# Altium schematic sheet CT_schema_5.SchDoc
size 411 x 401 mm
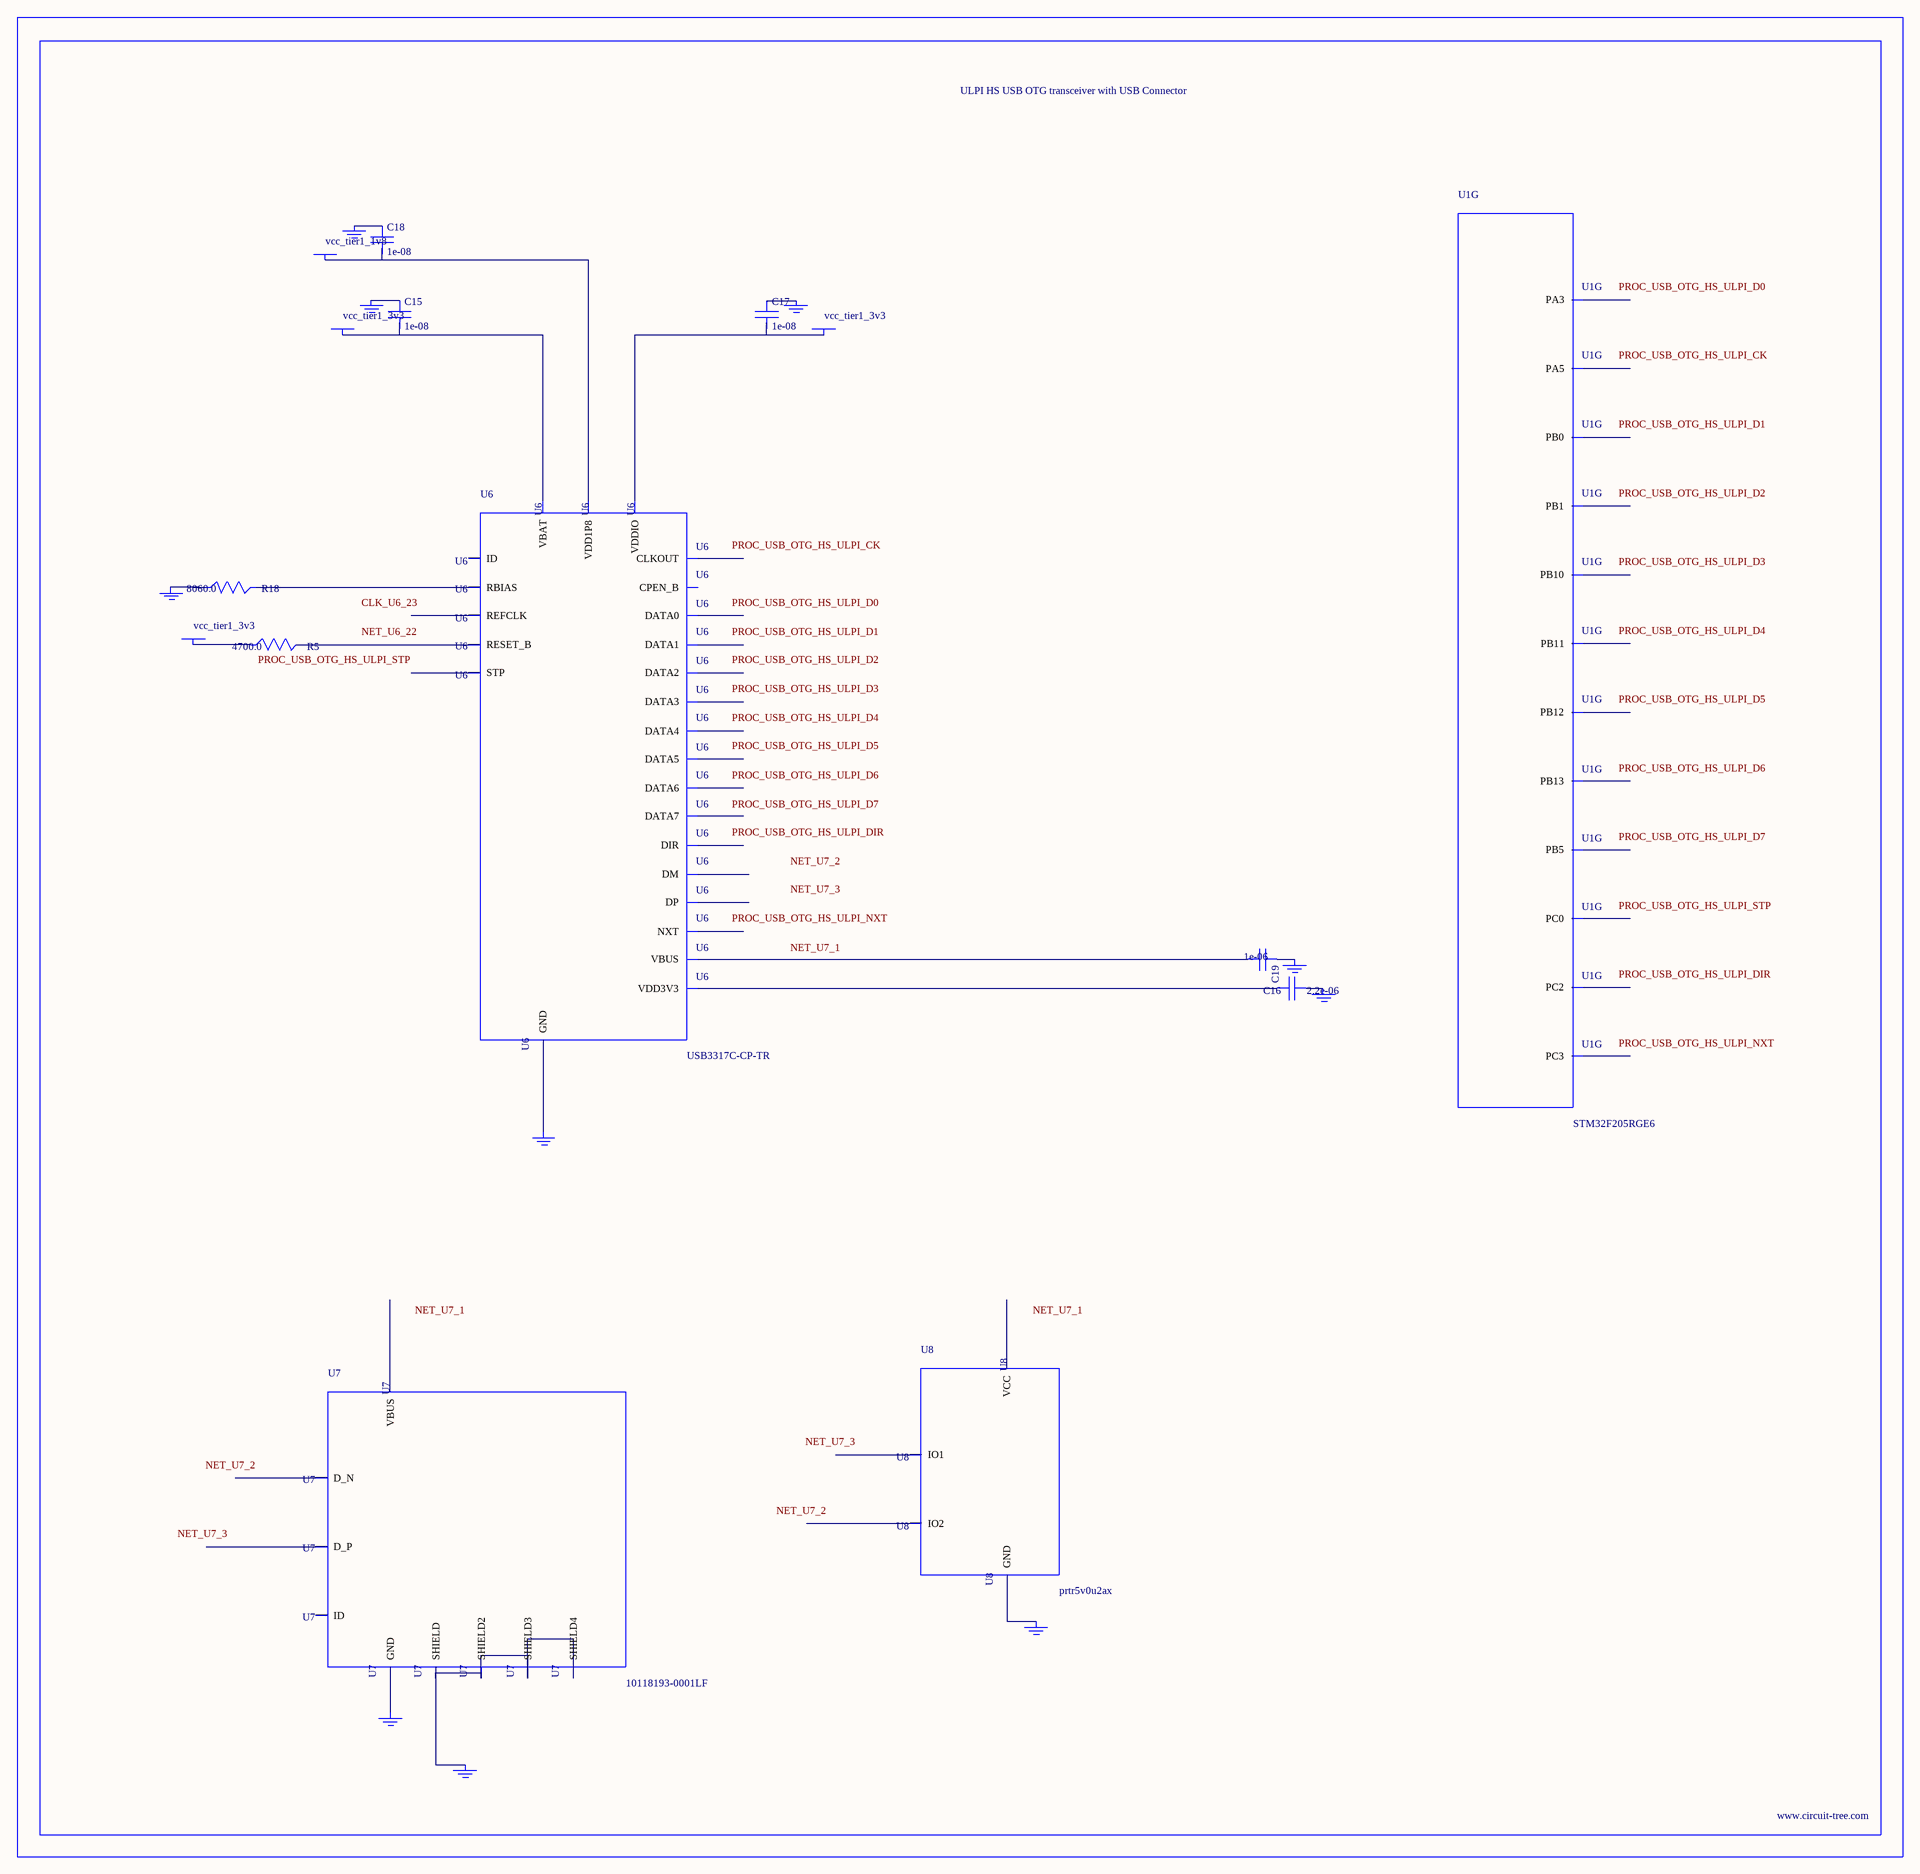
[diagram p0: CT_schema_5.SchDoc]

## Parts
BORDER4  (no value)
C15  1e-08  [C0402]
C16  2.2e-06  [C0603]
C17  1e-08  [C0402]
C18  1e-08  [C0402]
C19  1e-06  [C0603]
GND_INSTANCE_4_0  (no value)
GND_INSTANCE_4_1  (no value)
GND_INSTANCE_4_2  (no value)
GND_INSTANCE_4_3  (no value)
GND_INSTANCE_4_4  (no value)
GND_INSTANCE_4_5  (no value)
GND_INSTANCE_4_6  (no value)
GND_INSTANCE_4_7  (no value)
GND_INSTANCE_4_8  (no value)
GND_INSTANCE_4_9  (no value)
POWER_INSTANCE_4_0  vcc_tier1_3v3
POWER_INSTANCE_4_1  vcc_tier1_3v3
POWER_INSTANCE_4_2  vcc_tier1_1v8
POWER_INSTANCE_4_3  vcc_tier1_3v3
R5  4700.0  [R0603]
R18  8060.0  [R0603]
U1  STM32F205RGE6  [EWLCSP66]  (part G of 7)
U6  USB3317C-CP-TR  [QFN-24]
U7  10118193-0001LF  [FCI_10118193-0001LF]
U8  prtr5v0u2ax  [SOT143B]

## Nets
NetC15_1: C15.1 GND_INSTANCE_4_1.0(GND)
NetC15_2: C15.2 POWER_INSTANCE_4_0.0(PWR) U6.3(VBAT)
NetC16_1: C16.1 GND_INSTANCE_4_2.0(GND)
NetC16_2: C16.2 U6.4(VDD3V3)
NetC17_1: C17.1 GND_INSTANCE_4_3.0(GND)
NetC17_2: C17.2 POWER_INSTANCE_4_1.0(PWR) U6.17(VDDIO)
NetC18_1: C18.1 GND_INSTANCE_4_4.0(GND)
NetC18_2: C18.2 POWER_INSTANCE_4_2.0(PWR) U6.21(VDD1P8)
NetC19_1: C19.1 GND_INSTANCE_4_0.0(GND)
NetC19_2: C19.2 U6.2(VBUS)
NetGND_INSTANCE_4_5_0: GND_INSTANCE_4_5.0(GND) R18.1
NetGND_INSTANCE_4_6_0: GND_INSTANCE_4_6.0(GND) U6.25(GND)
NetGND_INSTANCE_4_7_0: GND_INSTANCE_4_7.0(GND) U7.6(SHIELD) U7.7(SHIELD2) U7.8(SHIELD3) U7.9(SHIELD4)
NetGND_INSTANCE_4_8_0: GND_INSTANCE_4_8.0(GND) U7.5(GND)
NetGND_INSTANCE_4_9_0: GND_INSTANCE_4_9.0(GND) U8.1(GND)
NetPOWER_INSTANCE_4_3_0: POWER_INSTANCE_4_3.0(PWR) R5.1
NetR5_2: R5.2 U6.22(RESET_B)
NetR18_2: R18.2 U6.24(RBIAS)

Not connected (* = marked no-connect by the designer): U1 A5(PB5) D7(PC2) G7(PA3) G8(PC3) G9(PC0) H2(PB13) H3(PB10) H6(PA5) J1(PB12) J2(PB11) J5(PB1) J6(PB0); U6 1(ID) 5(DM) 6(DP) 7(CPEN_B) 8(DATA7) 9(DATA6) 10(DATA5) 11(DATA4) 12(CLKOUT) 13(DATA3) 14(DATA2) 15(DATA1) 16(DATA0) 18(NXT) 19(DIR) 20(STP) 23(REFCLK); U7 1(VBUS) 2(D_N) 3(D_P) 4(ID); U8 2(IO1) 3(IO2) 4(VCC)

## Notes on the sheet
- Labels drawn without touching a wire or pin: CLK_U6_23, NET_U6_22, NET_U7_1, NET_U7_2, NET_U7_3, PROC_USB_OTG_HS_ULPI_CK, PROC_USB_OTG_HS_ULPI_D0, PROC_USB_OTG_HS_ULPI_D1, PROC_USB_OTG_HS_ULPI_D2, PROC_USB_OTG_HS_ULPI_D3, PROC_USB_OTG_HS_ULPI_D4, PROC_USB_OTG_HS_ULPI_D5, PROC_USB_OTG_HS_ULPI_D6, PROC_USB_OTG_HS_ULPI_D7, PROC_USB_OTG_HS_ULPI_DIR, PROC_USB_OTG_HS_ULPI_NXT, PROC_USB_OTG_HS_ULPI_STP

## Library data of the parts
BORDER4 = BORDER_PAGE4
C15 C17 C18 = C0402C103K3RAC
C16 = C0603C225K8RACTU
C19 = C0603C105K3RACTU
GND_INSTANCE_4_0-GND_INSTANCE_4_9 = GND
POWER_INSTANCE_4_0-POWER_INSTANCE_4_3 = PWR
R5 = RC0603JR-074K7L
R18 = ERJ-3EKF8061V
